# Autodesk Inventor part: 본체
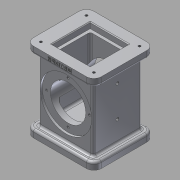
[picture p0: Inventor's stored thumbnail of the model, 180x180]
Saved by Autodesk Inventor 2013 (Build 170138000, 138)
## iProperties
Created: 2017-08
Part Number: 본체
Material: 알루미늄 6061
Document SubType Name: Modeling
Designer: Administrator
Density: 2.71 g/cm^3
Mass: 872.323 g
Surface Area: 642.251 cm^2
Volume: 321.89 cm^3
Author: Administrator
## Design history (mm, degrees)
sketch "스케치2"
  geometry: L1 (-37, -54)-(37, -54); L2 (37, -54)-(37, 54); L3 (37, 54)-(-37, 54); L4 (-37, 54)-(-37, -54); L5 (-37, -54)-(37, 54); L6 (37, -54)-(-37, 54); 3 further points
  constraints: 12 end point, 3 midpoint, 2 parallel, 1 coincident, 1 horizontal, 1 perpendicular
  dimensions: "d0" = 74 distance of L2.end L3.end; "d2" = 108 distance of L3.end L1.start
extrude "돌출1" new body sketch "스케치2" stored distance "d3" = 66; taper "d4" = 0 deg
sketch "스케치3"
  geometry: L1 (74, -66)-(74, 0) reference; L2 (0, 0)-(74, 0) reference; L3 (0, -66)-(0, 0) reference; L4 (74, -66)-(0, -66) reference; L5 (-9, -74)-(83, -74); L6 (83, -74)-(83, 8); L7 (83, 8)-(-9, 8); L8 (-9, 8)-(-9, -74); L9 (-9, -74)-(83, 8); L10 (83, -74)-(-9, 8); 1 further point
  constraints: 12 end point, 2 midpoint, 2 parallel, 1 horizontal, 1 perpendicular
  dimensions: "d5" = 92 distance of L6.end L7.end; "d7" = 82 distance of L7.end L5.start
extrude "돌출2" join sketch "스케치3" distance "d8" = 10; taper "d9" = 0 deg
sketch "스케치4"
  geometry: L1 (74, -66)-(74, 0) reference; L2 (0, 0)-(74, 0) reference; L3 (0, 0)-(0, -66) reference; L4 (74, -66)-(0, -66) reference; L5 (74, 0)-(0, 0) reference; L6 (74, -66)-(74, 0) reference; L7 (0, -66)-(74, -66) reference; L8 (0, 0)-(0, -66) reference; L9 (-9, -74)-(83, -74) reference; L10 (83, -74)-(83, 8) reference; L11 (83, 8)-(-9, 8) reference; L12 (-9, 8)-(-9, -74) reference; L13 (-9, -74)-(83, -74); L14 (83, -74)-(83, 8); L15 (83, 8)-(-9, 8); L16 (-9, 8)-(-9, -74); L17 (-9, -74)-(83, 8); L18 (83, -74)-(-9, 8); 1 further point
  constraints: 12 end point, 2 midpoint, 2 parallel, 1 horizontal, 1 perpendicular
extrude "돌출3" join sketch "스케치4" distance "d10" = 10; taper "d11" = 0 deg
sketch "스케치5"
  geometry: L1 (22, -65)-(70, -65); L2 (70, -65)-(70, -17); L3 (70, -17)-(22, -17); L4 (22, -17)-(22, -65); L5 (22, -65)-(70, -17); L6 (70, -65)-(22, -17); 3 further points
  constraints: 12 end point, 3 midpoint, 2 parallel, 1 coincident, 1 horizontal, 1 perpendicular
  dimensions: "d12" = 48 distance of L2.end L3.end; "d14" = 48 distance of L3.end L1.start
extrude "돌출4" cut sketch "스케치5" distance "d15" = 16; taper "d16" = 0 deg
sketch "스케치6"
  geometry: C1 r 35 at (0, 0); 1 further point
  constraints: 1 centre point, 1 coincident
  dimensions: "d17" = 70 diameter of C1
extrude "돌출5" cut sketch "스케치6" distance "d19" = 3; taper "d20" = 0 deg
sketch "스케치7"
  geometry: C1 r 35 at (0, 0); 1 further point
  constraints: 1 centre point, 1 coincident
  dimensions: "d21" = 70 diameter of C1
extrude "돌출6" cut sketch "스케치7" distance "d23" = 3; taper "d24" = 0 deg
sketch "스케치8"
  geometry: C1 r 35 at (0, 0) reference; C2 r 24 at (0, 0)
  constraints: 1 centre point, 1 coincident
  dimensions: "d25" = 48 diameter of C2
extrude "돌출7" cut sketch "스케치8" stored distance "d27" = 3; taper "d28" = 0 deg
sketch "스케치9"
  geometry: L1 (20, 15)-(72, 15); L2 (72, 15)-(72, 67); L3 (72, 67)-(20, 67); L4 (20, 67)-(20, 15); L5 (20, 15)-(72, 67); L6 (72, 15)-(20, 67); 1 further point
  constraints: 12 end point, 2 midpoint, 2 parallel, 1 horizontal, 1 perpendicular
  dimensions: "d29" = 52 distance of L3.end L1.start; "d31" = 52 distance of L2.end L3.end
extrude "돌출8" cut sketch "스케치9" distance "d32" = 8; taper "d33" = 0 deg
sketch "스케치10"
  geometry: L1 (24, 19)-(68, 19); L2 (68, 19)-(68, 63); L3 (68, 63)-(24, 63); L4 (24, 63)-(24, 19); L5 (24, 19)-(68, 63); L6 (68, 19)-(24, 63); 1 further point
  constraints: 12 end point, 2 midpoint, 2 parallel, 1 horizontal, 1 perpendicular
  dimensions: "d34" = 44 distance of L2.end L3.end; "d36" = 44 distance of L3.end L1.start
extrude "돌출9" cut sketch "스케치10" distance "d37" = 74; taper "d38" = 0 deg
sketch "스케치11" dims "d39" = 58
  geometry: C1 r 24 at (0, 0) reference; C2 r 35 at (0, 0) reference; C3 r 2.847 at (0, 29); 1 further point
  constraints: 2 vertical alignment, 1 centre point, 1 coincident, 2 other
sketch "스케치12" dims "d41" = 58
  geometry: C1 r 24 at (0, 0) reference; C2 r 35 at (0, 0) reference; C3 r 3.611 at (0, -29); 1 further point
  constraints: 2 vertical alignment, 1 centre point, 1 coincident, 2 other
hole "구멍1" sketch "스케치11" diameter "d43" = 3.242; stored, may be unused: countersink angle "d47" = 90 deg, drill point angle "d49" = 118 deg; dims "d44" = 4, "d45" = 4, "d46" = 2, "d48" = 6
hole "구멍2" sketch "스케치12" diameter "d50" = 3.242; stored, may be unused: countersink angle "d54" = 90 deg, drill point angle "d56" = 118 deg; dims "d51" = 4, "d52" = 4, "d53" = 2, "d55" = 6
sketch "스케치13"
  geometry: C1 r 3.159 at (10, 10); 1 further point
  constraints: 1 centre point
  dimensions: "d60" = 36 horizontal distance of point (46, 41) C1.centre; "d61" = 31 vertical distance of C1.centre point (46, 41)
sketch "스케치14"
  geometry: C1 r 3.159 at (82, -72) reference; 1 further point
hole "구멍3" sketch "스케치14" at (82, -72) diameter "d62" = 3.242; stored, may be unused: countersink angle "d66" = 90 deg, drill point angle "d68" = 118 deg; dims "d63" = 4, "d64" = 4, "d65" = 2, "d67" = 6
hole "구멍4" sketch "스케치13" diameter "d69" = 3.242; stored, may be unused: countersink angle "d73" = 90 deg, drill point angle "d75" = 118 deg; dims "d70" = 4, "d71" = 4, "d72" = 2, "d74" = 6
fillet "모깎기1" dims "d88" = 10
fillet "모깎기2" dims "d89" = 3
fillet "모깎기3" dims "d90" = 3
fillet "모깎기4" dims "d91" = 3
fillet "모깎기5" dims "d92" = 3
fillet "모깎기6" dims "d93" = 3
fillet "모깎기7" dims "d94" = 3
sketch "스케치15"
  geometry: L1 (95, 61)-(95, -1) reference; C1 r 7.226 at (57, 30); C2 r 13.45 at (15, 30); 1 further point
  constraints: 2 centre point, 2 horizontal alignment
  dimensions: "d95" = 38 distance from line of C1.centre L1; "d96" = 42 distance of C2.centre C1.centre
hole "구멍5" sketch "스케치15" at (15, 30), (57, 30) diameter "d97" = 4.134; stored, may be unused: countersink angle "d101" = 90 deg, drill point angle "d103" = 118 deg; dims "d98" = 4, "d99" = 4, "d100" = 2, "d102" = 19.75
chamfer "모따기1" distance "d104" = 1; stored, may be unused: second distance "d105" = 2, angle "d106" = 45 deg
fillet "모깎기8" dims "d107" = 3
sketch "스케치17"
  geometry: L1 (0, 0)-(72, 0) reference; L2 (8.67, -1.598)-(63.33, -1.598); L3 (63.33, -1.598)-(63.33, -6.402); L4 (63.33, -6.402)-(8.67, -6.402); L5 (8.67, -6.402)-(8.67, -1.598); L6 (8.67, -4)-(63.33, -4); L7 (36, -1.598)-(36, -6.402); L8 (-10, 0)-(-10, -7) reference; 1 further point
  constraints: 4 end point, 4 midpoint, 2 other
  dimensions: "d110" = 4 distance between parallel lines of L1 L6; "d111" = 46 distance between parallel lines of L8 L7
extrude "돌출10" join sketch "스케치17" distance "d112" = 0.5; taper "d113" = 0 deg
node "솔리드1"
pattern_circular "원형 패턴1" dims angle "d58" = 360 deg
pattern_linear "직사각형 패턴1" dims "d78" = 72, "d81" = 62
pattern_linear "직사각형 패턴2" dims "d84" = 72, "d87" = 62
node "투영된 루프1"
